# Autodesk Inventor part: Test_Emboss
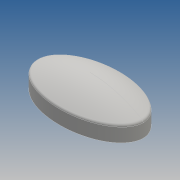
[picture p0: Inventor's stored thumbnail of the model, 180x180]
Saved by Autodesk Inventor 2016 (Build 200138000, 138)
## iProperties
Created: 2015-09
Part Number: Test_Emboss
Material: Generic
Document SubType Name: Modeling
Designer: julian.chica
Density: 1 g/cm^3
Appearance: Default
Author: julian.chica
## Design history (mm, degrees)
sketch "Sketch2" dims "d0" = 35, "d1" = 20
  geometry: 2 further points; 1 other entity
  constraints: 1 coincident, 2 other
extrude "Extrusion1" new body sketch "Sketch2" distance "d2" = 10; taper "d3" = 0 deg
workpoint "Work Point1"
  workplane "Work Plane1"
loft "Loft1" dims "d5" = 0, "d6" = 90 deg, "d7" = 10, "d8" = 90 deg
  node "Edges1"
fillet "Fillet1" dims "d9" = 2
body "Solid1"
